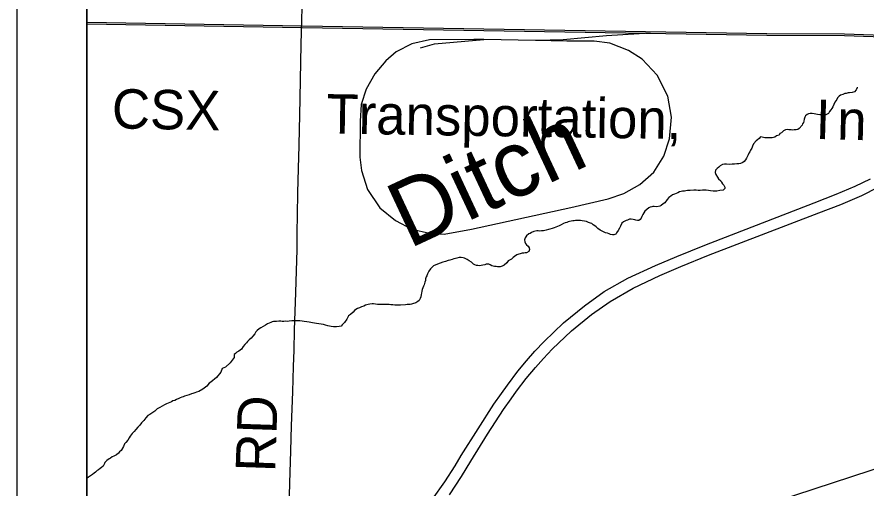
# Model space of a CAD drawing. Extents: x 0 to 34, y 0 to 22.
# Drawn here: x 23.417 to 24.635, y 17.233 to 17.91 of the extents above; entities that cross this region are included whole.
import ezdxf

# ---------------------------------------------------------------- set-up
doc = ezdxf.new("R2010")
doc.units = 0
for name, color, linetype in [('GM_X_County_Road', 7, 'Continuous'), ('GM_X_County_Road_Text', 7, 'Continuous'), ('GM_X_Minor_River', 7, 'Continuous'), ('GM_X_Minor_River_Text', 7, 'Continuous'), ('GM_X_Rail_Line', 7, 'Continuous'), ('GM_X_Rail_Line_Text', 7, 'Continuous'), ('GM_X_Township_Road', 7, 'Continuous'), ('GM_X_US_Route', 7, 'Continuous'), ('SH_Data', 7, 'Continuous')]:
    doc.layers.add(name, color=color, linetype=linetype)

msp = doc.modelspace()

# ---------------------------------------------------------------- linework, layer by layer
at = {"layer": 'GM_X_County_Road'}
msp.add_lwpolyline([(23.806, 17.1679), (23.8082, 17.2406), (23.8097, 17.2866), (23.8107, 17.3226), (23.8123, 17.3717), (23.8135, 17.4078), (23.8143, 17.4314), (23.815, 17.46), (23.8165, 17.5141), (23.8184, 17.5758), (23.8185, 17.5998), (23.8191, 17.6259), (23.8198, 17.6576), (23.8206, 17.6924), (23.8215, 17.7254), (23.822, 17.749), (23.8223, 17.7683), (23.8245, 17.8702), (23.8251, 17.9053), (23.8261, 17.942)], dxfattribs=at)
at = {"layer": 'GM_X_Minor_River'}
for points in [[(24.6221, 17.809), (24.6213, 17.8067), (24.6213, 17.8071), (24.6205, 17.8052), (24.6182, 17.8026), (24.6147, 17.8015), (24.6109, 17.8009), (24.609, 17.8009), (24.6063, 17.8002), (24.6044, 17.7999), (24.6014, 17.7988), (24.5983, 17.7978), (24.596, 17.7963), (24.594, 17.7937), (24.5928, 17.7915), (24.5901, 17.7877), (24.5869, 17.781), (24.5857, 17.7787), (24.5841, 17.7765), (24.5825, 17.7743), (24.5809, 17.7713), (24.579, 17.7702), (24.5763, 17.7691), (24.5729, 17.7688), (24.5706, 17.7692), (24.5683, 17.7693), (24.5649, 17.7698), (24.5627, 17.7702), (24.5604, 17.771), (24.5574, 17.7715), (24.5547, 17.7715), (24.5524, 17.7708), (24.5501, 17.7698), (24.5478, 17.7679), (24.547, 17.766), (24.5461, 17.763), (24.5453, 17.7604), (24.5449, 17.7585), (24.5437, 17.7566), (24.5433, 17.7547), (24.539, 17.7499), (24.5367, 17.7485), (24.5344, 17.7478), (24.5317, 17.7478), (24.5294, 17.7475), (24.5275, 17.7476), (24.5241, 17.748), (24.5222, 17.7481), (24.5192, 17.7478), (24.5165, 17.7463), (24.5134, 17.7437), (24.5111, 17.7427), (24.5102, 17.7404), (24.5064, 17.739), (24.5037, 17.7375), (24.5018, 17.7368), (24.4999, 17.7365), (24.4976, 17.7362), (24.495, 17.7362), (24.4927, 17.7363), (24.4893, 17.7364), (24.4859, 17.7372), (24.4832, 17.7377), (24.4813, 17.7354), (24.4789, 17.7336), (24.477, 17.7321), (24.4731, 17.7277), (24.4719, 17.7243), (24.4707, 17.7217), (24.4691, 17.7187), (24.4679, 17.7164), (24.4667, 17.7142), (24.4655, 17.7119), (24.4643, 17.7093), (24.4631, 17.707), (24.4619, 17.7048), (24.4599, 17.7022), (24.458, 17.7007), (24.4545, 17.6993), (24.4522, 17.699), (24.4492, 17.699), (24.4462, 17.6987), (24.4427, 17.6984), (24.4389, 17.6982), (24.4344, 17.6983), (24.4317, 17.6983), (24.429, 17.698), (24.4256, 17.6962), (24.4236, 17.6944), (24.4213, 17.6925), (24.419, 17.6899), (24.4185, 17.6865), (24.4192, 17.6835), (24.4214, 17.68), (24.4232, 17.6777), (24.4262, 17.6745), (24.4273, 17.6726), (24.4287, 17.6703), (24.4306, 17.6684), (24.432, 17.6653), (24.432, 17.6634)], [(24.432, 17.6634), (24.4296, 17.6612), (24.4251, 17.6605), (24.4205, 17.6599), (24.4171, 17.6596), (24.4152, 17.6596), (24.4118, 17.6601), (24.4087, 17.6606), (24.4053, 17.661), (24.4027, 17.6611), (24.4, 17.6612), (24.397, 17.6609), (24.3939, 17.6609), (24.3909, 17.661), (24.3875, 17.6611), (24.3825, 17.6608), (24.3787, 17.6606), (24.3761, 17.6603), (24.3741, 17.6599), (24.3715, 17.6596), (24.3696, 17.6593), (24.3673, 17.659), (24.3646, 17.6575), (24.3623, 17.6564), (24.36, 17.6553), (24.3569, 17.6543), (24.3546, 17.6528), (24.3519, 17.6506), (24.3495, 17.6476), (24.346, 17.6432), (24.3437, 17.6417), (24.3406, 17.6391), (24.3387, 17.638), (24.3348, 17.6374), (24.331, 17.6375), (24.3291, 17.6375), (24.3272, 17.6372), (24.3249, 17.6369), (24.323, 17.6358), (24.3176, 17.631), (24.316, 17.6287), (24.3144, 17.6261), (24.3132, 17.6235), (24.312, 17.6212), (24.3108, 17.619), (24.3089, 17.6175), (24.307, 17.6176), (24.3047, 17.618), (24.3028, 17.6184), (24.3006, 17.6189), (24.2979, 17.6197), (24.2956, 17.6194), (24.2926, 17.6183), (24.2907, 17.6176), (24.2887, 17.6165), (24.2868, 17.6158), (24.2845, 17.614), (24.2825, 17.6095), (24.2809, 17.6065), (24.2793, 17.6031), (24.2769, 17.6001), (24.2757, 17.5982), (24.2731, 17.5972), (24.2712, 17.5972), (24.2681, 17.5973), (24.2662, 17.5985), (24.264, 17.5993), (24.261, 17.6001), (24.258, 17.6014), (24.2531, 17.6038), (24.2501, 17.6061), (24.2475, 17.6085), (24.2456, 17.61), (24.2434, 17.6116), (24.2412, 17.6132), (24.2393, 17.6136), (24.2366, 17.6148), (24.2336, 17.616), (24.231, 17.6165), (24.2276, 17.6173), (24.2253, 17.6174), (24.223, 17.6174), (24.2204, 17.6175), (24.2181, 17.6176), (24.2162, 17.6172), (24.2143, 17.6173), (24.2116, 17.6166), (24.2093, 17.6163), (24.2074, 17.6156), (24.2055, 17.6149), (24.2032, 17.6142), (24.2005, 17.6131), (24.1974, 17.6116), (24.1944, 17.6102), (24.1921, 17.6091), (24.1898, 17.608), (24.1875, 17.6073), (24.1844, 17.6063), (24.1809, 17.6052), (24.179, 17.6045), (24.176, 17.6038)], [(24.176, 17.6038), (24.1741, 17.6031), (24.1718, 17.6028), (24.1691, 17.6029), (24.1668, 17.6025), (24.1642, 17.6026), (24.1623, 17.6027), (24.1581, 17.602), (24.155, 17.6002), (24.1527, 17.5991), (24.1508, 17.5984), (24.1477, 17.5954), (24.1457, 17.5925), (24.1449, 17.5898), (24.1452, 17.5868), (24.1463, 17.5848), (24.1477, 17.5829), (24.1499, 17.5806), (24.1514, 17.5786), (24.1517, 17.576), (24.1509, 17.573), (24.1474, 17.5711), (24.1455, 17.5712), (24.1436, 17.5709), (24.1413, 17.5705), (24.1387, 17.5698), (24.1364, 17.5691), (24.1337, 17.5681), (24.1306, 17.5659), (24.1286, 17.5644), (24.1263, 17.5622), (24.1232, 17.5607), (24.1213, 17.5597), (24.1193, 17.5567), (24.1155, 17.5533), (24.1128, 17.5519), (24.1097, 17.5512), (24.1078, 17.5509), (24.1059, 17.5509), (24.104, 17.5514), (24.1017, 17.5518), (24.0999, 17.5522), (24.098, 17.5527), (24.0957, 17.5539), (24.0935, 17.5547), (24.09, 17.5548), (24.0877, 17.5541), (24.0851, 17.5534), (24.0824, 17.5531), (24.0797, 17.5527), (24.0778, 17.5528), (24.0759, 17.5532), (24.0737, 17.554), (24.0718, 17.5548), (24.0685, 17.5576), (24.0655, 17.5596), (24.0625, 17.5615), (24.0606, 17.5627), (24.0587, 17.5635), (24.0568, 17.564), (24.0538, 17.5644), (24.0512, 17.5645), (24.0477, 17.5634), (24.0458, 17.5631), (24.0435, 17.5624), (24.0408, 17.5617), (24.0378, 17.5607), (24.0351, 17.56), (24.0316, 17.5589), (24.0278, 17.5579), (24.024, 17.5565), (24.0198, 17.555), (24.014, 17.5525), (24.0117, 17.5499), (24.0101, 17.5481), (24.0077, 17.5451), (24.0066, 17.5428), (24.0054, 17.541), (24.0045, 17.5383), (24.0037, 17.5365), (24.0029, 17.5338), (24.0025, 17.5316), (24.0017, 17.5293), (24.0012, 17.527), (24.0008, 17.5251), (24, 17.5233), (23.9988, 17.521), (23.998, 17.5184), (23.9975, 17.5161), (23.9971, 17.5135), (23.9963, 17.5112), (23.9958, 17.5082), (23.995, 17.5055), (23.9938, 17.5029), (23.9915, 17.5011), (23.9891, 17.4996), (23.9872, 17.4989), (23.9853, 17.4986), (23.9826, 17.4975), (23.9807, 17.4972), (23.9784, 17.4968)], [(23.9784, 17.4968), (23.9762, 17.4969), (23.9739, 17.4966), (23.967, 17.496), (23.9644, 17.4961), (23.9609, 17.4962), (23.9587, 17.4962), (23.956, 17.4967), (23.953, 17.4967), (23.9507, 17.4968), (23.948, 17.4969), (23.9454, 17.4969), (23.9408, 17.4971), (23.9386, 17.4971), (23.9367, 17.4972), (23.934, 17.4972), (23.931, 17.4973), (23.9283, 17.4978), (23.926, 17.4978), (23.923, 17.4975), (23.9207, 17.4968), (23.9165, 17.4958), (23.9142, 17.4947), (23.9111, 17.4936), (23.908, 17.4922), (23.9054, 17.4911), (23.903, 17.49), (23.9007, 17.4886), (23.8988, 17.486), (23.8953, 17.4826), (23.8922, 17.4808), (23.8914, 17.479), (23.8898, 17.476), (23.8866, 17.4711), (23.8831, 17.4678), (23.8816, 17.4659), (23.8789, 17.4652), (23.8751, 17.4649), (23.8709, 17.465), (23.8675, 17.4655), (23.8648, 17.466), (23.8626, 17.4664), (23.8592, 17.4672), (23.8565, 17.4681), (23.8531, 17.4689), (23.8497, 17.4694), (23.8463, 17.4699), (23.8433, 17.4703), (23.8406, 17.4708), (23.8384, 17.4712), (23.8357, 17.4716), (23.8327, 17.4721), (23.8289, 17.4726), (23.8259, 17.473), (23.8225, 17.4735), (23.8194, 17.4736), (23.8176, 17.4736), (23.8111, 17.4734), (23.8073, 17.4731), (23.8042, 17.4728), (23.8023, 17.4729), (23.7997, 17.4726), (23.797, 17.4726), (23.7951, 17.4731), (23.7921, 17.4731), (23.789, 17.4728), (23.7849, 17.4726), (23.7829, 17.4719), (23.781, 17.4711), (23.7783, 17.4701), (23.776, 17.469), (23.7733, 17.4675), (23.7664, 17.4635), (23.7641, 17.4621), (23.761, 17.4595), (23.7594, 17.4576), (23.7578, 17.455), (23.7551, 17.4517), (23.7524, 17.4487), (23.7496, 17.4461), (23.7473, 17.4439), (23.7457, 17.442), (23.7434, 17.4395), (23.741, 17.4369), (23.7387, 17.4327), (23.7348, 17.4302), (23.7321, 17.4283), (23.7301, 17.4265), (23.7282, 17.4254), (23.7281, 17.4209), (23.7226, 17.4134), (23.7156, 17.4071), (23.711, 17.405), (23.7093, 17.3997), (23.7027, 17.3923), (23.6949, 17.3856), (23.6922, 17.3838), (23.6891, 17.3797), (23.6833, 17.3753), (23.6775, 17.372), (23.6741, 17.371)], [(23.6741, 17.371), (23.6717, 17.3699), (23.6691, 17.3692), (23.6668, 17.3685), (23.6637, 17.3674), (23.6603, 17.3664), (23.6572, 17.3653), (23.6549, 17.3646), (23.653, 17.3639), (23.6507, 17.3628), (23.6488, 17.3621), (23.6457, 17.3607), (23.643, 17.3592), (23.6403, 17.3585), (23.6384, 17.3574), (23.6361, 17.3564), (23.6334, 17.3553), (23.6311, 17.3542), (23.6284, 17.3528), (23.6249, 17.351), (23.6215, 17.3491), (23.618, 17.347), (23.6145, 17.3436), (23.6102, 17.3411), (23.6072, 17.3389), (23.6045, 17.3374), (23.6017, 17.3341), (23.5986, 17.3304), (23.5955, 17.327), (23.5927, 17.3237), (23.59, 17.3207), (23.5873, 17.3177), (23.5849, 17.3148), (23.5818, 17.3118), (23.5806, 17.3099), (23.579, 17.3077), (23.5775, 17.3055), (23.5755, 17.3021), (23.5727, 17.2987), (23.5708, 17.2969), (23.5695, 17.2931), (23.566, 17.2875), (23.5637, 17.2853), (23.5625, 17.2834), (23.5594, 17.2812), (23.5555, 17.2794), (23.5532, 17.278), (23.5509, 17.2765), (23.549, 17.2754), (23.5455, 17.2729), (23.5428, 17.2703), (23.542, 17.2684), (23.5404, 17.265), (23.538, 17.2628), (23.5361, 17.2613), (23.5338, 17.2595), (23.5318, 17.2584), (23.5291, 17.2562), (23.5272, 17.2547), (23.5249, 17.2529), (23.5221, 17.2507), (23.5194, 17.2492), (23.5175, 17.2474), (23.5167, 17.2467)]]:
    msp.add_lwpolyline(points, dxfattribs=at)
at = {"layer": 'GM_X_Rail_Line'}
msp.add_line((24.1606, 17.8761), (24.0864, 17.8774), dxfattribs=at)
for points in [[(23.5167, 17.9025), (23.826, 17.8974), (24.4922, 17.8863), (24.6036, 17.8856), (24.6861, 17.883)], [(23.5167, 17.9), (23.826, 17.8949), (24.4922, 17.8838), (24.6036, 17.8831), (24.6861, 17.8805)], [(24.3252, 17.8866), (24.2623, 17.8826), (24.2, 17.8773), (24.1628, 17.876), (24.1606, 17.8761)], [(24.0864, 17.8774), (24.0722, 17.8777), (24.0083, 17.8773), (23.983, 17.8713), (23.9608, 17.8598), (23.9458, 17.8471), (23.93, 17.8284), (23.9177, 17.8062), (23.9105, 17.784), (23.9092, 17.7601), (23.9084, 17.7088), (23.9109, 17.6892), (23.9197, 17.6623), (23.9372, 17.636), (23.9596, 17.6175), (23.9832, 17.6054), (24.0087, 17.5994), (24.0295, 17.5982), (24.0687, 17.6052), (24.2111, 17.6362), (24.2646, 17.6486), (24.2872, 17.6562), (24.3104, 17.6693), (24.3301, 17.6872), (24.3445, 17.7098), (24.3527, 17.7347), (24.3556, 17.7659), (24.3505, 17.7961), (24.3352, 17.8263), (24.3135, 17.8493), (24.2941, 17.8619), (24.2674, 17.8724), (24.2448, 17.875), (24.2056, 17.8752), (24.1606, 17.8761)], [(23.9955, 17.8654), (24.0155, 17.8715), (24.0864, 17.8774)], [(23.5167, 16.8913), (23.7996, 16.983), (25.7008, 17.6061)]]:
    msp.add_lwpolyline(points, dxfattribs=at)
at = {"layer": 'GM_X_Township_Road'}
msp.add_lwpolyline([(24.7215, 18.313), (24.6064, 18.5004), (24.5339, 18.5567), (24.4603, 18.5785), (24.3637, 18.583), (24.2856, 18.5622), (24.1994, 18.53), (24.12, 18.538), (24.0257, 18.5782), (23.9624, 18.631), (23.898, 18.7), (23.8186, 18.7551), (23.7407, 18.7883), (23.6866, 18.7918), (23.6395, 18.7618), (23.6269, 18.7216), (23.6328, 18.5687), (23.627, 18.5353), (23.5995, 18.4744), (23.5512, 18.4226), (23.5167, 18.4074), (23.5167, 14.1)], dxfattribs=at)
at = {"layer": 'GM_X_US_Route'}
for points in [[(24.0128, 17.2176), (24.0304, 17.2422), (24.0454, 17.2654), (24.0541, 17.2799), (24.0781, 17.3182), (24.1009, 17.3537), (24.1116, 17.3693), (24.1202, 17.3812), (24.1351, 17.4012), (24.1475, 17.4159), (24.1596, 17.43), (24.1728, 17.444), (24.2007, 17.4708), (24.2306, 17.4949), (24.2589, 17.5156), (24.2929, 17.5348), (24.3328, 17.5532), (24.3633, 17.5661), (24.4034, 17.582), (24.5605, 17.6432), (24.5918, 17.6555), (24.6191, 17.6667), (24.6411, 17.6774)], [(24.037, 17.2238), (24.0542, 17.2498), (24.0679, 17.2722), (24.0919, 17.3106), (24.1147, 17.3463), (24.1254, 17.3614), (24.1333, 17.3724), (24.1471, 17.3909), (24.1606, 17.4066), (24.1718, 17.4193), (24.1845, 17.433), (24.2122, 17.4593), (24.2407, 17.4828), (24.2676, 17.5014), (24.3005, 17.5205), (24.3391, 17.5388), (24.3691, 17.5515), (24.4086, 17.5677), (24.5668, 17.6287), (24.5984, 17.6407), (24.6286, 17.6537), (24.6522, 17.6654)]]:
    msp.add_lwpolyline(points, dxfattribs=at)
at = {"layer": 'SH_Data'}
for points in [[(23.4167, 21), (30.4167, 21), (30.4167, 14), (23.4167, 14)], [(23.5167, 20.9), (30.3167, 20.9), (30.3167, 14.1), (23.5167, 14.1)]]:
    msp.add_lwpolyline(points, close=True, dxfattribs=at)

# ---------------------------------------------------------------- texts
at = {"layer": 'GM_X_County_Road_Text'}
msp.add_text('RD', height=0.05682, rotation=88.0373, dxfattribs=at).set_placement((23.787, 17.2557))
at = {"layer": 'GM_X_Minor_River_Text'}
msp.add_text('Ditch', height=0.09474, rotation=25.0385, dxfattribs=at).set_placement((23.9789, 17.5765))
at = {"layer": 'GM_X_Rail_Line_Text'}
for s, height, rotation, p in [('CSX', 0.05663, 358.9397, (23.5524, 17.75)), ('Transportation,', 0.056629, 359.0895, (23.8602, 17.7426)), ('I', 0.0566, 358.4107, (24.5618, 17.7348)), ('n', 0.0566, 358.567, (24.5928, 17.7339))]:
    msp.add_text(s, height=height, rotation=rotation, dxfattribs=at).set_placement(p)

doc.saveas('drawing.dxf')
